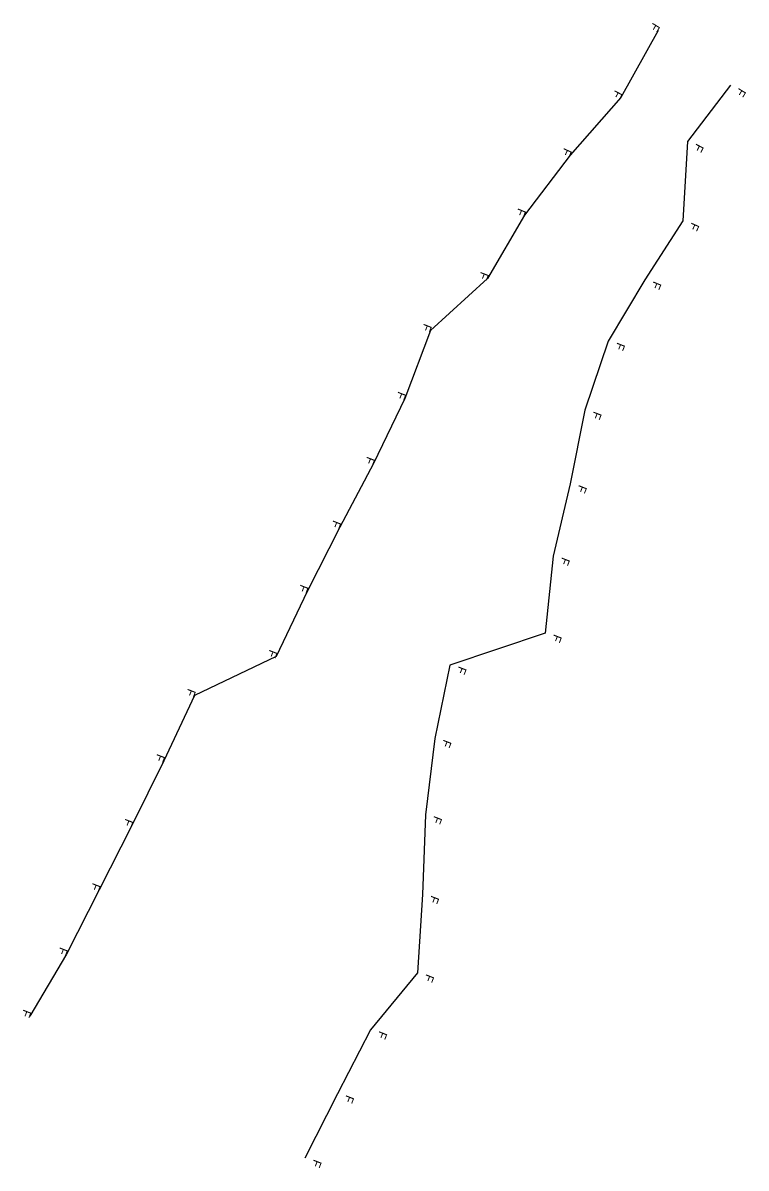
# Model space of a CAD drawing. Extents: x -76 to 2348158, y -10 to 845166.
# Drawn here: x 2347656 to 2348158, y 844372 to 845166 of the extents above; entities that cross this region are included whole.
import ezdxf

# ---------------------------------------------------------------- set-up
doc = ezdxf.new("R2010")
doc.units = 0
for name, color, linetype in [('Prop SS Cut Text', 7, 'Continuous'), ('Prop SS Fill Line', 7, 'Continuous'), ('Prop SS Fill Text', 7, 'Continuous')]:
    doc.layers.add(name, color=color, linetype=linetype)

msp = doc.modelspace()

# ---------------------------------------------------------------- linework, layer by layer
at = {"layer": 'Prop SS Fill Line'}
for p, q in [((2348096.69, 845161.2), (2348070.8, 845114.65)), ((2348146.78, 845123.21), (2348117.14, 845084.25)), ((2348070.8, 845114.65), (2348035.78, 845074.78)), ((2348117.14, 845084.25), (2348113.81, 845029.19)), ((2348035.78, 845074.78), (2348004.09, 845033.15)), ((2348004.09, 845033.15), (2347978.31, 844989.16)), ((2348113.81, 845029.19), (2348087.38, 844988.23)), ((2347978.31, 844989.16), (2347938.8, 844953.2)), ((2348087.38, 844988.23), (2348062.17, 844945.67)), ((2347938.8, 844953.2), (2347921.04, 844906.09)), ((2348062.17, 844945.67), (2348045.91, 844897.85)), ((2347921.04, 844906.09), (2347899.41, 844860.99)), ((2348045.91, 844897.85), (2348035.69, 844846.85)), ((2347899.41, 844860.99), (2347875.98, 844816.82)), ((2348035.69, 844846.85), (2348023.92, 844796.65)), ((2347875.98, 844816.82), (2347853.31, 844772.25)), ((2348023.92, 844796.65), (2348018.33, 844743.26)), ((2347853.31, 844772.25), (2347831.79, 844727.09)), ((2348018.33, 844743.26), (2347952.26, 844721.12)), ((2347831.79, 844727.09), (2347775.17, 844700.07)), ((2347952.26, 844721.12), (2347941.81, 844670.24)), ((2347775.17, 844700.07), (2347753.82, 844654.81)), ((2347941.81, 844670.24), (2347935.29, 844617.33)), ((2347753.82, 844654.81), (2347731.85, 844609.89)), ((2347935.29, 844617.33), (2347933.25, 844562.1)), ((2347731.85, 844609.89), (2347709.16, 844565.33)), ((2347709.16, 844565.33), (2347686.46, 844520.78)), ((2347933.25, 844562.1), (2347929.77, 844507.62)), ((2347686.46, 844520.78), (2347661.11, 844477.6)), ((2347929.77, 844507.62), (2347897.24, 844468.15)), ((2347897.24, 844468.15), (2347874.27, 844423.74)), ((2347874.27, 844423.74), (2347851.75, 844379.09))]:
    msp.add_line(p, q, dxfattribs=at)

# ---------------------------------------------------------------- texts
at = {"layer": 'Prop SS Cut Text'}
for rotation, p in [(238.8221, (2348152.91, 845121.81)), (242.73498, (2348123.34, 845083.27)), (245.70954, (2348120.06, 845028.54)), (247.66096, (2348093.65, 844987.78)), (248.58924, (2348068.44, 844945.33)), (248.6741, (2348052.19, 844897.52)), (248.6741, (2348041.97, 844846.52)), (248.6741, (2348030.2, 844796.32)), (248.6741, (2348024.6, 844742.93)), (248.6741, (2347958.54, 844720.79)), (248.6741, (2347948.08, 844669.91)), (248.6741, (2347941.57, 844616.99)), (248.6741, (2347939.53, 844561.77)), (248.6741, (2347936.05, 844507.28)), (248.6741, (2347903.51, 844467.81)), (248.6741, (2347880.55, 844423.4)), (248.6741, (2347858.03, 844378.76))]:
    msp.add_text('F', height=6, rotation=rotation, dxfattribs=at).set_placement(p)
at = {"layer": 'Prop SS Fill Text'}
for rotation, p in [(238.8221, (2348093.25, 845167.05)), (242.73498, (2348066.98, 845120.25)), (245.70954, (2348031.66, 845080.17)), (247.66096, (2347999.8, 845038.4)), (248.58924, (2347973.93, 844994.34)), (248.6741, (2347934.42, 844958.37)), (248.6741, (2347916.66, 844911.27)), (248.6741, (2347895.02, 844866.17)), (248.6741, (2347871.59, 844821.99)), (248.6741, (2347848.92, 844777.43)), (248.6741, (2347827.4, 844732.26)), (248.6741, (2347770.78, 844705.24)), (248.6741, (2347749.44, 844659.99)), (248.6741, (2347727.47, 844615.06)), (248.6741, (2347704.78, 844570.5)), (248.6741, (2347682.08, 844525.95)), (248.6741, (2347656.72, 844482.78))]:
    msp.add_text('F', height=6, rotation=rotation, dxfattribs=at).set_placement(p)

doc.saveas('drawing.dxf')
